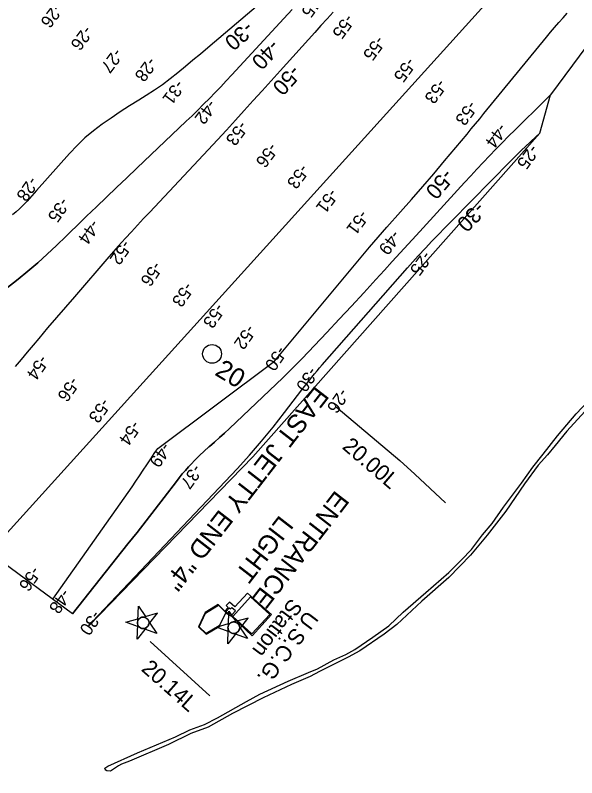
# Model space of a CAD drawing. Extents: x 3879599 to 3900814, y 146526 to 168888.
# Drawn here: x 3889730 to 3891224, y 152146 to 154174 of the extents above; entities that cross this region are included whole.
import ezdxf

# ---------------------------------------------------------------- set-up
doc = ezdxf.new("R2010")
doc.units = 0
for name, color, linetype in [('V-BLDG-IDEN', 7, 'Continuous'), ('V-BLDG-OTLN', 7, 'Continuous'), ('V-CHAN-DOCK', 7, 'Continuous'), ('V-CHAN-NAID', 7, 'Continuous'), ('V-LEVE-TOET', 7, 'Continuous'), ('V-RIVR-IDEN', 7, 'Continuous'), ('V-RIVR-JETY', 7, 'Continuous'), ('V-RIVR-MILE', 7, 'Continuous'), ('V-RIVR-RANG', 7, 'Continuous'), ('V-STRM-FMON', 7, 'Continuous'), ('V-TOPO-DPTH', 7, 'Continuous'), ('V-TOPO-MAJR', 7, 'Continuous'), ('V-TOPO-MAJR-IDEN', 7, 'Continuous'), ('V-TOPO-MINR', 7, 'Continuous'), ('V-TOPO-MINR-IDEN', 7, 'Continuous')]:
    doc.layers.add(name, color=color, linetype=linetype)

msp = doc.modelspace()

# ---------------------------------------------------------------- linework, layer by layer
at = {"layer": 'V-BLDG-OTLN'}
for points in [[(3890356.2, 152626.8), (3890407.2, 152580.2), (3890359.6, 152528.1), (3890308.6, 152574.7)], [(3890270.6, 152604.4), (3890290, 152585.1), (3890272.1, 152549.4), (3890237.7, 152529.5), (3890219.5, 152547.2), (3890236.2, 152583.7)]]:
    msp.add_lwpolyline(points, close=True, dxfattribs=at)
at = {"layer": 'V-CHAN-DOCK'}
for points in [[(3890348, 152636.7), (3890314.2, 152600), (3890300, 152613), (3890291.4, 152603.7), (3890296.6, 152598.9), (3890287.6, 152588.9), (3890269.8, 152606.6), (3890235.3, 152584.8), (3890217.8, 152547), (3890237.6, 152527.7), (3890272.8, 152548), (3890290.4, 152583.1), (3890305.4, 152575), (3890360.3, 152523.3), (3890411.8, 152580.1), (3890348, 152636.7)], [(3890290.6, 152586.6), (3890306.2, 152578.8), (3890316, 152589.3), (3890306, 152597.5), (3890302, 152593.9), (3890300, 152597.4), (3890290.6, 152586.6)]]:
    msp.add_lwpolyline(points, dxfattribs=at)
at = {"layer": 'V-CHAN-NAID'}
for points in [[(3890056.1, 152563.7), (3890057.6, 152601.9), (3890076.2, 152574.1), (3890071.6, 152572.8), (3890071, 152572.8), (3890069.8, 152572.8), (3890068.9, 152572.8), (3890067.9, 152572.7), (3890067, 152572.5), (3890066, 152572.3), (3890065.2, 152572), (3890064.3, 152571.7), (3890063.4, 152571.3), (3890062.6, 152570.8), (3890061.9, 152570.4), (3890061.2, 152570), (3890060.3, 152569.2), (3890059.7, 152568.7), (3890059, 152568), (3890058.5, 152567.4), (3890057.9, 152566.7), (3890057.4, 152566), (3890056.9, 152565.3), (3890056.5, 152564.4)], [(3890084.7, 152553.1), (3890108.4, 152583.2), (3890071.6, 152572.8), (3890072.7, 152572.6), (3890073.6, 152572.5), (3890074.6, 152572.2), (3890075.6, 152571.8), (3890076.3, 152571.6), (3890077, 152571.2), (3890077.7, 152570.9), (3890078.3, 152570.5), (3890079.1, 152570), (3890079.7, 152569.5), (3890080.5, 152568.8), (3890081.1, 152568.2), (3890081.8, 152567.4), (3890082.4, 152566.6), (3890083, 152565.8), (3890083.5, 152565), (3890083.9, 152564.3), (3890084.2, 152563.5), (3890084.6, 152562.5), (3890084.8, 152561.7), (3890085, 152560.9), (3890085.2, 152560.1), (3890085.3, 152559.2), (3890085.4, 152558.5), (3890085.4, 152557.4), (3890085.4, 152556.6), (3890085.3, 152555.7), (3890085.1, 152554.7), (3890084.9, 152553.9)], [(3890297.2, 152550.8), (3890298.6, 152589), (3890317.2, 152561.2), (3890312.6, 152559.9), (3890312, 152559.9), (3890310.9, 152560), (3890309.9, 152559.9), (3890308.9, 152559.8), (3890308, 152559.6), (3890307.1, 152559.4), (3890306.3, 152559.2), (3890305.3, 152558.8), (3890304.5, 152558.4), (3890303.6, 152557.9), (3890302.9, 152557.5), (3890302.2, 152557.1), (3890301.3, 152556.4), (3890300.7, 152555.8), (3890300, 152555.1), (3890299.5, 152554.5), (3890298.9, 152553.8), (3890298.4, 152553.1), (3890298, 152552.4), (3890297.5, 152551.5)], [(3890055.7, 152552.6), (3890055.5, 152547.8), (3890024.1, 152559.3), (3890056.3, 152568.4), (3890056.1, 152563.7), (3890055.8, 152562.9), (3890055.5, 152562), (3890055.2, 152560.9), (3890055, 152560), (3890054.9, 152558.9), (3890054.9, 152557.8), (3890054.9, 152556.8), (3890054.9, 152556), (3890055.1, 152555), (3890055.3, 152554.1), (3890055.5, 152553.2)], [(3890325.8, 152540.3), (3890349.4, 152570.3), (3890312.6, 152559.9), (3890313.7, 152559.7), (3890314.6, 152559.6), (3890315.6, 152559.3), (3890316.7, 152558.9), (3890317.3, 152558.7), (3890318, 152558.3), (3890318.7, 152558), (3890319.4, 152557.6), (3890320.1, 152557.1), (3890320.7, 152556.6), (3890321.5, 152555.9), (3890322.1, 152555.4), (3890322.8, 152554.5), (3890323.5, 152553.7), (3890324, 152552.9), (3890324.5, 152552.2), (3890324.9, 152551.4), (3890325.2, 152550.6), (3890325.6, 152549.6), (3890325.9, 152548.8), (3890326.1, 152548), (3890326.2, 152547.2), (3890326.3, 152546.3), (3890326.4, 152545.6), (3890326.4, 152544.5), (3890326.4, 152543.8), (3890326.3, 152542.8), (3890326.2, 152541.8), (3890326, 152541)], [(3890077.9, 152544.4), (3890054.3, 152514.4), (3890055.7, 152552.6), (3890056, 152551.8), (3890056.4, 152550.8), (3890056.8, 152550), (3890057.4, 152549.2), (3890057.9, 152548.4), (3890058.5, 152547.7), (3890059.1, 152547), (3890059.7, 152546.4), (3890060.5, 152545.7), (3890061.4, 152545.1), (3890062.3, 152544.5), (3890063.1, 152544), (3890064.1, 152543.5), (3890065.2, 152543.1), (3890066.2, 152542.8), (3890066.9, 152542.6), (3890068, 152542.5), (3890069, 152542.4), (3890070.1, 152542.3), (3890071, 152542.3), (3890072, 152542.4), (3890073.1, 152542.6), (3890074.2, 152542.9), (3890075.2, 152543.2), (3890076.2, 152543.6), (3890076.9, 152543.9)], [(3890084.7, 152553.1), (3890087.7, 152556.9), (3890106.3, 152529.1), (3890074.9, 152540.7), (3890077.9, 152544.4), (3890078.6, 152544.9), (3890079.5, 152545.5), (3890080.3, 152546.2), (3890081, 152546.9), (3890081.4, 152547.3), (3890081.9, 152547.9), (3890082.5, 152548.6), (3890082.9, 152549.1), (3890083.4, 152550), (3890083.7, 152550.6), (3890084.1, 152551.4), (3890084.4, 152552.1), (3890084.6, 152552.6)], [(3890296.7, 152539.7), (3890296.6, 152534.9), (3890265.1, 152546.4), (3890297.3, 152555.6), (3890297.2, 152550.8), (3890296.8, 152550), (3890296.6, 152549.2), (3890296.3, 152548), (3890296.1, 152547.1), (3890295.9, 152546), (3890295.9, 152544.9), (3890295.9, 152543.9), (3890296, 152543.1), (3890296.1, 152542.1), (3890296.3, 152541.2), (3890296.5, 152540.3)], [(3890318.9, 152531.5), (3890295.3, 152501.5), (3890296.7, 152539.7), (3890297, 152538.9), (3890297.5, 152537.9), (3890297.9, 152537.2), (3890298.4, 152536.3), (3890299, 152535.5), (3890299.5, 152534.8), (3890300.2, 152534.1), (3890300.7, 152533.5), (3890301.6, 152532.8), (3890302.4, 152532.2), (3890303.3, 152531.6), (3890304.1, 152531.1), (3890305.1, 152530.7), (3890306.2, 152530.3), (3890307.2, 152529.9), (3890308, 152529.8), (3890309, 152529.6), (3890310, 152529.5), (3890311.1, 152529.4), (3890312.1, 152529.4), (3890313, 152529.5), (3890314.1, 152529.7), (3890315.2, 152530), (3890316.2, 152530.3), (3890317.2, 152530.7), (3890318, 152531)], [(3890325.8, 152540.3), (3890328.7, 152544), (3890347.4, 152516.2), (3890316, 152527.8), (3890318.9, 152531.5), (3890319.6, 152532), (3890320.5, 152532.6), (3890321.3, 152533.3), (3890322.1, 152534), (3890322.5, 152534.4), (3890323, 152535), (3890323.5, 152535.7), (3890323.9, 152536.3), (3890324.4, 152537.1), (3890324.7, 152537.7), (3890325.1, 152538.5), (3890325.4, 152539.2), (3890325.6, 152539.7)]]:
    msp.add_lwpolyline(points, close=True, dxfattribs=at)
for centre in [(3890070.1, 152557.6), (3890311.2, 152544.7)]:
    msp.add_circle(centre, 15.3, dxfattribs=at)
at = {"layer": 'V-LEVE-TOET'}
msp.add_line((3890247.3, 152363.7), (3890089.1, 152508.1), dxfattribs=at)
msp.add_lwpolyline([(3890583.8, 153132.7), (3890752.9, 152989.6), (3890793, 152953.2), (3890874.6, 152876.9)], dxfattribs=at)
at = {"layer": 'V-RIVR-JETY'}
for points in [[(3891468.8, 153396.7), (3891390.1, 153293.7), (3891298.6, 153181.1), (3891245.6, 153120.2), (3891197.3, 153067.3), (3891166.7, 153029.4), (3891146.1, 153004.8), (3891120.7, 152977.2), (3891084.9, 152927.5), (3891035.4, 152854.5), (3890985.4, 152790.9), (3890941, 152738), (3890883.7, 152678.2), (3890811.7, 152615.5), (3890745, 152553.6), (3890711.6, 152527.1), (3890646.5, 152483.4), (3890615.7, 152466.3), (3890539.2, 152428.2), (3890514.7, 152415)], [(3890533.8, 152435), (3890577.5, 152459), (3890609.1, 152473.5), (3890633.6, 152486.7), (3890681.7, 152519.1), (3890724.2, 152549.6), (3890762.4, 152586.1), (3890822, 152638.4), (3890883.5, 152691.5), (3890917.6, 152725.2), (3890943.4, 152752.9), (3890972.9, 152791.9), (3890999.1, 152822.2), (3891028.8, 152865), (3891077, 152929.3), (3891107.1, 152972.1), (3891134, 153006.6), (3891172.4, 153055.2), (3891222.1, 153113.5), (3891254.3, 153147.2)], [(3890233.1, 152287.6), (3890268.1, 152305.1), (3890345.3, 152348.1), (3890380.7, 152368.3), (3890456.1, 152402.9), (3890510, 152425.6), (3890533.8, 152435)], [(3890514.7, 152415), (3890464.9, 152394), (3890389.9, 152358.5), (3890307.8, 152316.6), (3890243, 152280.5), (3890197, 152263.2)], [(3889968.4, 152170.9), (3889976.7, 152176), (3890055.1, 152211.4), (3890156.5, 152254.8), (3890194.2, 152273.1), (3890233.1, 152287.6)], [(3890197, 152263.2), (3890137.9, 152233.7), (3890034.1, 152189.6), (3890012.6, 152181.7), (3890004.7, 152177.4), (3889983.3, 152163.5), (3889973.8, 152163.8), (3889971.1, 152165.6), (3889969.6, 152168.3), (3889968.4, 152170.9)]]:
    msp.add_lwpolyline(points, dxfattribs=at)
at = {"layer": 'V-RIVR-MILE'}
msp.add_circle((3890253.5, 153273.1), 25, dxfattribs=at)
at = {"layer": 'V-RIVR-RANG'}
msp.add_lwpolyline([(3887950.4, 150855.4), (3895383.9, 159071.9)], dxfattribs=at)
at = {"layer": 'V-TOPO-DPTH'}
for p, q in [((3891125.5, 153860.2), (3891153.5, 153962.5)), ((3889882.4, 152581.8), (3889298.2, 153011.4))]:
    msp.add_line(p, q, dxfattribs=at)
for points in [[(3891753.9, 154772.9), (3891153.5, 153962.5), (3891138.5, 153947.6), (3891059.5, 153869.3), (3891042.3, 153852.2), (3891025.2, 153834.9), (3891008.3, 153817.4), (3890991.5, 153799.8), (3890974.8, 153782.2), (3890958.2, 153764.4), (3890941.6, 153746.6), (3890925.2, 153728.7), (3890796.3, 153588.1), (3890775.2, 153565.1), (3890754.1, 153542), (3890733, 153518.8), (3890711.9, 153495.7), (3890689.4, 153470.9), (3890657, 153435.5), (3890624.4, 153400.2), (3890591.5, 153365.2), (3890558.6, 153330.3), (3890492.9, 153261.2), (3890476.1, 153243.9), (3890459.1, 153226.7), (3890441.9, 153209.7), (3890424.5, 153193), (3890299.8, 153074.6), (3890286.8, 153062.4), (3890273.6, 153050.4), (3890260.2, 153038.5), (3890246.6, 153026.9), (3890245, 153025.5), (3890232.4, 153014.4), (3890220.1, 153003), (3890208.2, 152991.1), (3890196.7, 152978.9), (3890191.1, 152972.7), (3890182.7, 152963.3), (3890174.4, 152953.7), (3890166.4, 152943.8), (3890158.6, 152933.9), (3890126.2, 152891.5), (3890102.3, 152860.3), (3890078.2, 152829.2), (3890054, 152798.2), (3890029.6, 152767.4), (3889882.4, 152581.8)], [(3890435.7, 154251.9), (3890242.5, 154087.6), (3890222.6, 154070.8), (3890202.7, 154054.1), (3890182.7, 154037.4), (3890162.7, 154020.8), (3890142.3, 154004.6), (3890121.5, 153989.1), (3890100, 153974.5), (3890078.2, 153960.4), (3890058.5, 153948.3), (3890033.7, 153932.8), (3890009.2, 153917), (3889985, 153900.6), (3889961, 153884), (3889937.8, 153866.3), (3889915.5, 153847.6), (3889894.6, 153827.5), (3889874.5, 153806.4), (3889786.9, 153707.5), (3889780.6, 153700.4), (3889774.2, 153693.4), (3889767.7, 153686.4), (3889761.3, 153679.5), (3889757.8, 153675.8), (3889749.4, 153667.2), (3889740.9, 153658.7), (3889732, 153650.6), (3889723, 153642.6)], [(3890435.7, 154251.9), (3890242.5, 154087.6), (3890222.6, 154070.8), (3890202.7, 154054.1), (3890182.7, 154037.4), (3890162.7, 154020.8), (3890142.3, 154004.6), (3890121.5, 153989.1), (3890100, 153974.5), (3890078.2, 153960.4), (3890058.5, 153948.3), (3890033.7, 153932.8), (3890009.2, 153917), (3889985, 153900.6), (3889961, 153884), (3889937.8, 153866.3), (3889915.5, 153847.6), (3889894.6, 153827.5), (3889874.5, 153806.4), (3889786.9, 153707.5), (3889780.6, 153700.4), (3889774.2, 153693.4), (3889767.7, 153686.4), (3889761.3, 153679.5), (3889757.8, 153675.8), (3889749.4, 153667.2), (3889740.9, 153658.7), (3889732, 153650.6), (3889723, 153642.6)], [(3889704.7, 153446.2), (3889737.4, 153472.1), (3889763.8, 153493.6), (3889789.7, 153515.6), (3889814.9, 153538.3), (3889839.7, 153561.6), (3889865.2, 153586.3), (3889878.8, 153599.5), (3889892.5, 153612.8), (3889906.1, 153626), (3889919.8, 153639.2), (3889946, 153664.5), (3889972.8, 153690.3), (3889999.6, 153716.1), (3890026.5, 153741.8), (3890053.5, 153767.5), (3890184.6, 153891.8), (3890200.3, 153906.8), (3890215.8, 153921.9), (3890231.2, 153937.2), (3890246.4, 153952.5), (3890261.5, 153968.1), (3890276.6, 153983.7), (3890291.4, 153999.5), (3890306.2, 154015.3), (3890444.8, 154165.5), (3890467.1, 154189.7)], [(3889704.7, 153446.2), (3889737.4, 153472.1), (3889763.8, 153493.6), (3889789.7, 153515.6), (3889814.9, 153538.3), (3889839.7, 153561.6), (3889865.2, 153586.3), (3889878.8, 153599.5), (3889892.5, 153612.8), (3889906.1, 153626), (3889919.8, 153639.2), (3889946, 153664.5), (3889972.8, 153690.3), (3889999.6, 153716.1), (3890026.5, 153741.8), (3890053.5, 153767.5), (3890184.6, 153891.8), (3890200.3, 153906.8), (3890215.8, 153921.9), (3890231.2, 153937.2), (3890246.4, 153952.5), (3890261.5, 153968.1), (3890276.6, 153983.7), (3890291.4, 153999.5), (3890306.2, 154015.3), (3890444.8, 154165.5), (3890467.1, 154189.7)], [(3891153.5, 153962.5), (3891138.5, 153947.6), (3891059.5, 153869.3), (3891042.3, 153852.2), (3891025.2, 153834.9), (3891008.3, 153817.4), (3890991.5, 153799.8), (3890974.8, 153782.2), (3890958.2, 153764.4), (3890941.6, 153746.6), (3890925.2, 153728.7), (3890796.3, 153588.1), (3890775.2, 153565.1), (3890754.1, 153542), (3890733, 153518.8), (3890711.9, 153495.7), (3890689.4, 153470.9), (3890657, 153435.5), (3890624.4, 153400.2), (3890591.5, 153365.2), (3890558.6, 153330.3), (3890492.9, 153261.2), (3890476.1, 153243.9), (3890459.1, 153226.7), (3890441.9, 153209.7), (3890424.5, 153193), (3890299.8, 153074.6), (3890286.8, 153062.4), (3890273.6, 153050.4), (3890260.2, 153038.5), (3890246.6, 153026.9), (3890245, 153025.5), (3890232.4, 153014.4), (3890220.1, 153003), (3890208.2, 152991.1), (3890196.7, 152978.9), (3890191.1, 152972.7), (3890182.7, 152963.3), (3890174.4, 152953.7), (3890166.4, 152943.8), (3890158.6, 152933.9), (3890126.2, 152891.5), (3890102.3, 152860.3), (3890078.2, 152829.2), (3890054, 152798.2), (3890029.6, 152767.4), (3889882.4, 152581.8)], [(3891125.5, 153860.2), (3890362.1, 152999.7), (3889925.5, 152550.1), (3889928.8, 152553.9), (3889930.4, 152555.8), (3889932.1, 152557.6), (3889935.5, 152561.3), (3890320.1, 152967.7), (3890353.1, 153003.8), (3890385.3, 153040.5), (3890416.3, 153078.3), (3890446.5, 153116.8), (3890492.7, 153177.7), (3890499.3, 153186.2), (3890505.8, 153194.7), (3890512.5, 153203.1), (3890519.2, 153211.4), (3890526, 153219.7), (3890532.8, 153228), (3890539.8, 153236.1), (3890546.8, 153244.2), (3890773.7, 153502.2), (3890780.7, 153510.2), (3890787.8, 153518.1), (3890795, 153526), (3890802.3, 153533.8), (3890821.6, 153554.6), (3890838.6, 153572.7), (3890855.7, 153590.7), (3890872.9, 153608.6), (3890890.3, 153626.3), (3891047.5, 153785.5), (3891057.3, 153795.4), (3891067.2, 153805.2), (3891077.2, 153814.8), (3891087.3, 153824.4), (3891099.7, 153836.1), (3891116, 153851.4), (3891125.5, 153860.2)], [(3889925.5, 152550.1), (3889928.8, 152553.9), (3889930.4, 152555.8), (3889932.1, 152557.6), (3889935.5, 152561.3), (3890320.1, 152967.7), (3890353.1, 153003.8), (3890385.3, 153040.5), (3890416.3, 153078.3), (3890446.5, 153116.8), (3890492.7, 153177.7), (3890499.3, 153186.2), (3890505.8, 153194.7), (3890512.5, 153203.1), (3890519.2, 153211.4), (3890526, 153219.7), (3890532.8, 153228), (3890539.8, 153236.1), (3890546.8, 153244.2), (3890773.7, 153502.2), (3890780.7, 153510.2), (3890787.8, 153518.1), (3890795, 153526), (3890802.3, 153533.8), (3890821.6, 153554.6), (3890838.6, 153572.7), (3890855.7, 153590.7), (3890872.9, 153608.6), (3890890.3, 153626.3), (3891047.5, 153785.5), (3891057.3, 153795.4), (3891067.2, 153805.2), (3891077.2, 153814.8), (3891087.3, 153824.4), (3891099.7, 153836.1), (3891116, 153851.4), (3891125.5, 153860.2)]]:
    msp.add_lwpolyline(points, dxfattribs=at)
at = {"layer": 'V-TOPO-MAJR'}
for points in [[(3890575.8, 154182.2), (3890559.5, 154164.3), (3890543.2, 154146.3), (3890527, 154128.4), (3890434.5, 154025.9), (3890410.7, 153999.6), (3890386.9, 153973.3), (3890363.2, 153947), (3890339.4, 153920.7), (3890315.6, 153894.5), (3890291.6, 153868.3), (3890267.6, 153842.3), (3890243.4, 153816.4), (3890087.7, 153650.3), (3890071.5, 153632.9), (3890055.3, 153615.5), (3890039.1, 153598.1), (3890023, 153580.7), (3890003.7, 153559.7), (3889997.3, 153552.7), (3889990.9, 153545.6), (3889984.7, 153538.5), (3889978.5, 153531.4), (3889887.3, 153425.3), (3889863.5, 153397.6), (3889839.8, 153369.9), (3889816.1, 153342.1), (3889792.5, 153314.3), (3889777.3, 153296.3), (3889761.4, 153277.4), (3889745.4, 153258.6), (3889729.4, 153239.7)], [(3889829.8, 152620.5), (3890040.7, 152919.7), (3890050.8, 152934.2), (3890060.8, 152948.8), (3890070.6, 152963.4), (3890080.3, 152978.2), (3890090.6, 152993.9), (3890095.1, 153000.8), (3890099.8, 153007.7), (3890104.4, 153014.5), (3890109.1, 153021.4), (3890419.6, 153253.4), (3890672.3, 153556.7), (3890683.7, 153570.2), (3890695.1, 153583.5), (3890706.7, 153596.8), (3890718.3, 153609.9), (3890754.7, 153650.6), (3890784.5, 153684.2), (3890814, 153718), (3890843.2, 153752.1), (3890872.1, 153786.3), (3890931.8, 153857.8), (3890943.1, 153871.4), (3890954.4, 153885), (3890965.7, 153898.7), (3890976.9, 153912.4), (3891143.2, 154116), (3891154, 154129), (3891164.9, 154141.8), (3891176, 154154.4), (3891187.2, 154166.9), (3891198.6, 154179.3)]]:
    msp.add_lwpolyline(points, dxfattribs=at)
at = {"layer": 'V-TOPO-MINR'}
for points in [[(3890435.7, 154251.9), (3890242.5, 154087.6), (3890222.6, 154070.8), (3890202.7, 154054.1), (3890182.7, 154037.4), (3890162.7, 154020.8), (3890142.3, 154004.6), (3890121.5, 153989.1), (3890100, 153974.5), (3890078.2, 153960.4), (3890058.5, 153948.3), (3890033.7, 153932.8), (3890009.2, 153917), (3889985, 153900.6), (3889961, 153884), (3889937.8, 153866.3), (3889915.5, 153847.6), (3889894.6, 153827.5), (3889874.5, 153806.4), (3889786.9, 153707.5), (3889780.6, 153700.4), (3889774.2, 153693.4), (3889767.7, 153686.4), (3889761.3, 153679.5), (3889757.8, 153675.8), (3889749.4, 153667.2), (3889740.9, 153658.7), (3889732, 153650.6), (3889723, 153642.6)], [(3890467.1, 154189.7), (3890444.8, 154165.5), (3890306.2, 154015.3), (3890291.4, 153999.5), (3890276.6, 153983.7), (3890261.5, 153968.1), (3890246.4, 153952.5), (3890231.2, 153937.2), (3890215.8, 153921.9), (3890200.3, 153906.8), (3890184.6, 153891.8), (3890053.5, 153767.5), (3890026.5, 153741.8), (3889999.6, 153716.1), (3889972.8, 153690.3), (3889946, 153664.5), (3889919.8, 153639.2), (3889906.1, 153626), (3889892.5, 153612.8), (3889878.8, 153599.5), (3889865.2, 153586.3), (3889839.7, 153561.6), (3889814.9, 153538.3), (3889789.7, 153515.6), (3889763.8, 153493.6), (3889737.4, 153472.1), (3889704.7, 153446.2)], [(3889882.4, 152581.8), (3890029.6, 152767.4), (3890054, 152798.2), (3890078.2, 152829.2), (3890102.3, 152860.3), (3890126.2, 152891.5), (3890158.6, 152933.9), (3890166.4, 152943.8), (3890174.4, 152953.7), (3890182.7, 152963.3), (3890191.1, 152972.7), (3890196.7, 152978.9), (3890208.2, 152991.1), (3890220.1, 153003), (3890232.4, 153014.4), (3890245, 153025.5), (3890246.6, 153026.9), (3890260.2, 153038.5), (3890273.6, 153050.4), (3890286.8, 153062.4), (3890299.8, 153074.6), (3890424.5, 153193), (3890441.9, 153209.7), (3890459.1, 153226.7), (3890476.1, 153243.9), (3890492.9, 153261.2), (3890558.6, 153330.3), (3890591.5, 153365.2), (3890624.4, 153400.2), (3890657, 153435.5), (3890689.4, 153470.9), (3890711.9, 153495.7), (3890733, 153518.8), (3890754.1, 153542), (3890775.2, 153565.1), (3890796.3, 153588.1), (3890925.2, 153728.7), (3890941.6, 153746.6), (3890958.2, 153764.4), (3890974.8, 153782.2), (3890991.5, 153799.8), (3891008.3, 153817.4), (3891025.2, 153834.9), (3891042.3, 153852.2), (3891059.5, 153869.3), (3891138.5, 153947.6), (3891153.5, 153962.5)], [(3889925.5, 152550.1), (3889928.8, 152553.9), (3889930.4, 152555.8), (3889932.1, 152557.6), (3889935.5, 152561.3), (3890320.1, 152967.7), (3890353.1, 153003.8), (3890385.3, 153040.5), (3890416.3, 153078.3), (3890446.5, 153116.8), (3890492.7, 153177.7), (3890499.3, 153186.2), (3890505.8, 153194.7), (3890512.5, 153203.1), (3890519.2, 153211.4), (3890526, 153219.7), (3890532.8, 153228), (3890539.8, 153236.1), (3890546.8, 153244.2), (3890773.7, 153502.2), (3890780.7, 153510.2), (3890787.8, 153518.1), (3890795, 153526), (3890802.3, 153533.8), (3890821.6, 153554.6), (3890838.6, 153572.7), (3890855.7, 153590.7), (3890872.9, 153608.6), (3890890.3, 153626.3), (3891047.5, 153785.5), (3891057.3, 153795.4), (3891067.2, 153805.2), (3891077.2, 153814.8), (3891087.3, 153824.4), (3891099.7, 153836.1), (3891116, 153851.4), (3891125.5, 153860.2)]]:
    msp.add_lwpolyline(points, dxfattribs=at)

# ---------------------------------------------------------------- texts
at = {"layer": 'V-BLDG-IDEN'}
for s, p in [('Station', (3890463.6, 152625.6)), ('U.S.C.G.', (3890505.7, 152593.1))]:
    msp.add_text(s, height=42, rotation=232.9925, dxfattribs=at).set_placement(p)
at = {"layer": 'V-CHAN-NAID'}
for s, p in [('EAST JETTY END "4"', (3890528.2, 153190.9)), ('ENTRANCE', (3890582.1, 152912.5)), ('LIGHT', (3890433.6, 152846.4))]:
    msp.add_text(s, height=50, rotation=232.244, dxfattribs=at).set_placement(p)
at = {"layer": 'V-RIVR-IDEN'}
msp.add_text('20', height=50, rotation=328.6701, dxfattribs=at).set_placement((3890258.2, 153218.6))
at = {"layer": 'V-RIVR-RANG'}
for s, rotation, p in [('-45', 233.6983, (3890527.5, 154236.2)), ('-26', 232.9683, (3889834.3, 154208.7)), ('-55', 233.6983, (3890609.8, 154179.3)), ('-26', 232.9683, (3889914.2, 154148.7)), ('-55', 233.6983, (3890691.4, 154121.6)), ('-27', 232.9683, (3889994.2, 154088.7)), ('-28', 233.1117, (3890084.6, 154065.2)), ('-55', 233.6983, (3890773.1, 154063.9)), ('-53', 233.6983, (3890855.2, 154006.8)), ('-31', 233.1117, (3890158.5, 154004.4)), ('-42', 233.1117, (3890244, 153952.1)), ('-53', 233.6983, (3890936.9, 153949)), ('-53', 233.1117, (3890326.9, 153895.2)), ('-44', 233.6983, (3891016.8, 153889.1)), ('-56', 233.1117, (3890406.7, 153836.9)), ('-25', 233.6983, (3891100.9, 153832.7)), ('-53', 233.1117, (3890489.6, 153780.3)), ('-28', 235.2513, (3889768.2, 153747.3)), ('-51', 233.1117, (3890566.9, 153715.3)), ('-35', 235.2513, (3889851.3, 153691.6)), ('-51', 233.1117, (3890648, 153658.1)), ('-44', 235.2513, (3889932.3, 153633)), ('-49', 233.1117, (3890733.6, 153604.7)), ('-52', 235.2513, (3890016.4, 153578.7)), ('-25', 233.1117, (3890816.7, 153549.2)), ('-56', 235.2513, (3890098.3, 153521.3)), ('-53', 235.2513, (3890181.8, 153466.3)), ('-53', 235.2513, (3890264.4, 153410)), ('-52', 235.2513, (3890346.9, 153353.4)), ('-50', 235.2513, (3890429, 153296.4)), ('-54', 234.6544, (3889796, 153272.4)), ('-30', 235.2513, (3890512.1, 153240.7)), ('-56', 234.6544, (3889877.9, 153214.5)), ('-26', 235.2513, (3890594.3, 153183.9)), ('-53', 234.6544, (3889960.7, 153157.7)), ('-54', 234.6544, (3890041.6, 153098.1)), ('-49', 234.6544, (3890122.1, 153039.7)), ('-37', 234.6544, (3890204.6, 152982.3)), ('-56', 235.0027, (3889774.9, 152710.3)), ('-48', 235.0027, (3889855, 152650.4)), ('-30', 235.0027, (3889936.4, 152593))]:
    msp.add_text(s, height=33.5, rotation=rotation, dxfattribs=at).set_placement(p)
at = {"layer": 'V-STRM-FMON'}
for s, rotation, p in [('20.00L', 319.4159, (3890597.4, 153022.9)), ('20.14L', 318.5648, (3890062.9, 152432.1))]:
    msp.add_text(s, height=42, rotation=rotation, dxfattribs=at).set_placement(p)
at = {"layer": 'V-TOPO-MAJR-IDEN'}
for rotation, p in [(227.9206, (3890465.1, 154044.4)), (229.4389, (3890870.9, 153768.5))]:
    msp.add_text('-50', height=41.5, rotation=rotation, dxfattribs=at).set_placement(p)
at = {"layer": 'V-TOPO-MINR-IDEN'}
for s, rotation, p in [('-30', 220.3589, (3890344.4, 154160.6)), ('-40', 227.2858, (3890410.1, 154112.5)), ('-30', 225.3682, (3890958, 153680.1))]:
    msp.add_text(s, height=41.5, rotation=rotation, dxfattribs=at).set_placement(p)

doc.saveas('drawing.dxf')
